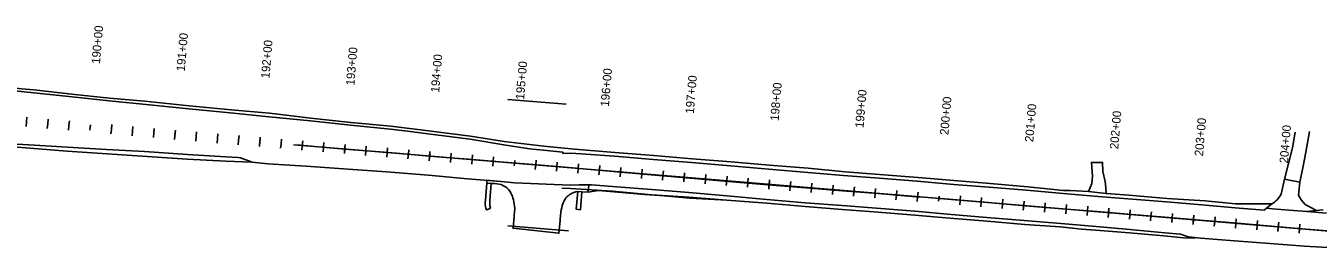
# Model space of a CAD drawing. Extents: x 20499880 to 20505309, y 7953507 to 7955507.
# Drawn here: x 20502629 to 20504147, y 7953670 to 7953931 of the extents above; entities that cross this region are included whole.
import ezdxf

# ---------------------------------------------------------------- set-up
doc = ezdxf.new("R2010")
doc.units = 0
for name, color, linetype in [('Alignment', 7, 'Continuous'), ('Curb', 7, 'Continuous'), ('Draft_0', 7, 'Continuous'), ('Entrance', 7, 'Continuous')]:
    doc.layers.add(name, color=color, linetype=linetype)

msp = doc.modelspace()

# ---------------------------------------------------------------- linework, layer by layer
at = {"layer": 'Alignment'}
for p, q in [((20502705.2, 7953814.8), (20502704.6, 7953808.7)), ((20502705.2, 7953814.8), (20502704.6, 7953808.7)), ((20502804.5, 7953803), (20502805, 7953808.5)), ((20502804.5, 7953803), (20502804.1, 7953797.6)), ((20502904.2, 7953794.7), (20502903.7, 7953789.3)), ((20502904.2, 7953794.7), (20502904.6, 7953800.2)), ((20503003.8, 7953786.4), (20503004.3, 7953791.8)), ((20503003.8, 7953786.4), (20503003.4, 7953781)), ((20503103.5, 7953778.1), (20503103, 7953772.6)), ((20503103.5, 7953778.1), (20503103.9, 7953783.5)), ((20503203.4, 7953772.8), (20503202.9, 7953766.7)), ((20503203.4, 7953772.8), (20503202.9, 7953766.7)), ((20503302.8, 7953761.5), (20503302.3, 7953756)), ((20503302.8, 7953761.5), (20503303.3, 7953766.9)), ((20503402.5, 7953753.1), (20503402, 7953747.7)), ((20503402.5, 7953753.1), (20503402.9, 7953758.6)), ((20503502.1, 7953744.8), (20503502.6, 7953750.3)), ((20503502.1, 7953744.8), (20503501.7, 7953739.4)), ((20503601.8, 7953736.5), (20503601.3, 7953731.1)), ((20503601.8, 7953736.5), (20503602.2, 7953741.9)), ((20503701.7, 7953731.2), (20503701.2, 7953725.1)), ((20503701.7, 7953731.2), (20503701.2, 7953725.1)), ((20503801.1, 7953719.9), (20503800.6, 7953714.4)), ((20503801.1, 7953719.9), (20503801.5, 7953725.3)), ((20503900.7, 7953711.6), (20503901.2, 7953717)), ((20503900.7, 7953711.6), (20503900.3, 7953706.1)), ((20504000.4, 7953703.2), (20503999.9, 7953697.8)), ((20504000.4, 7953703.2), (20504000.8, 7953708.7)), ((20504100, 7953694.9), (20504100.5, 7953700.4)), ((20504100, 7953694.9), (20504099.6, 7953689.5))]:
    msp.add_line(p, q, dxfattribs=at)
at = {"layer": 'Curb'}
for p, q in [((20503195.4, 7953844.6), (20503263.7, 7953838.9)), ((20504116.6, 7953787.9), (20504119.9, 7953806.1)), ((20504112.1, 7953769.2), (20504116.6, 7953787.9)), ((20504107.2, 7953750.8), (20504112.1, 7953769.2)), ((20504103.3, 7953733.3), (20504107.2, 7953750.8)), ((20504107.2, 7953750.8), (20504125.4, 7953747.6)), ((20504086.1, 7953717.1), (20504092.3, 7953721.9)), ((20503195.2, 7953696.3), (20503266.6, 7953690.4))]:
    msp.add_line(p, q, dxfattribs=at)
for points in [[(20502599.2, 7953860.1), (20502613.4, 7953858.2), (20502624.3, 7953857.2), (20502638.7, 7953856), (20502686.8, 7953850.5), (20502727.7, 7953846), (20502769, 7953842.4), (20502821.2, 7953837), (20502870.6, 7953832.3), (20502915.4, 7953828.5), (20502964.1, 7953822.6), (20503011.1, 7953817.6)], [(20504156.6, 7953711.2), (20504133.6, 7953713.2), (20504112.7, 7953714.7), (20504093.2, 7953716.3), (20504086.1, 7953717.1), (20504083.6, 7953714.6), (20504049.4, 7953717.4), (20504010.1, 7953720.8), (20503968.9, 7953724.2), (20503928.6, 7953727.3), (20503888.5, 7953730.8), (20503847.4, 7953734.3), (20503804.4, 7953737.9), (20503760.6, 7953741.4), (20503719.1, 7953744.8), (20503675.9, 7953748.5), (20503631.5, 7953752.1), (20503589.5, 7953755.4), (20503547.6, 7953758.8), (20503501.9, 7953762.8), (20503456.9, 7953766.5), (20503411.1, 7953770.4), (20503366, 7953774.1), (20503320.7, 7953777.8), (20503281.6, 7953780.8), (20503269, 7953781.5), (20503260.1, 7953781.3), (20503260, 7953782.6), (20503237.1, 7953784.9), (20503220.9, 7953786.7), (20503190.6, 7953791.2), (20503151.2, 7953797.9), (20503104.5, 7953803.8), (20503080.8, 7953807), (20503057.7, 7953809.7), (20503010.5, 7953814.4), (20502963.6, 7953819.3), (20502915.2, 7953824.2), (20502869.4, 7953828.7), (20502820.8, 7953833.4), (20502774.8, 7953838.1), (20502727.2, 7953842.9), (20502683.7, 7953847.7), (20502605, 7953855.9)], [(20503273.7, 7953786.1), (20503237.5, 7953789.7), (20503191, 7953795.2), (20503151.5, 7953801.3), (20503105.3, 7953807.3), (20503057.9, 7953813.2), (20503011.1, 7953817.6)], [(20504136.5, 7953807.1), (20504132.4, 7953782.5), (20504129.2, 7953766.4), (20504125.4, 7953747.6), (20504123.9, 7953732.1), (20504126.9, 7953726.7), (20504131.6, 7953721.3), (20504143.9, 7953714.5), (20504144.2, 7953713.9)], [(20502895, 7953771), (20502894.8, 7953770.8), (20502864.2, 7953772), (20502819, 7953774.4), (20502678, 7953783.9), (20502590, 7953791.1), (20502585.9, 7953791.2)], [(20503203, 7953746.5), (20503187.4, 7953748.3), (20503148, 7953751.4), (20503102.1, 7953755.6), (20503052.7, 7953759.7), (20503007.9, 7953762.8), (20502958.4, 7953766.1), (20502913.6, 7953768.9), (20502895, 7953771), (20502884.5, 7953774.9), (20502881.3, 7953776.1), (20502878.6, 7953776.4), (20502864.4, 7953777.3), (20502819.3, 7953780.1), (20502768.9, 7953783.3), (20502724.3, 7953785.9), (20502678.2, 7953788.5), (20502632.9, 7953791.3), (20502589.7, 7953793.5)], [(20503321, 7953782.2), (20503273.7, 7953786.1)], [(20503677.2, 7953752.9), (20503631.8, 7953756.3), (20503591.3, 7953759.6), (20503547.9, 7953763.8), (20503502.2, 7953767.6), (20503457.4, 7953771.5), (20503411.6, 7953774.8), (20503366.7, 7953778.8), (20503321, 7953782.2)], [(20503877.3, 7953736.5), (20503881.1, 7953745.7), (20503881.9, 7953754.6), (20503880.5, 7953770.7), (20503893.6, 7953770.7), (20503894, 7953760.1), (20503896.9, 7953748.4), (20503897.6, 7953740.9), (20503897.9, 7953734.2)], [(20504171.6, 7953670), (20504130.8, 7953672.4), (20504090.2, 7953675.6), (20504048.5, 7953678.4), (20504008.7, 7953681.6), (20503994, 7953683.1), (20503985, 7953686.5), (20503966.6, 7953687.9), (20503925.7, 7953691.8), (20503886.2, 7953695.4), (20503844.6, 7953699), (20503801.7, 7953702.5), (20503757.8, 7953706.1), (20503715.9, 7953709.6), (20503673.4, 7953713.3), (20503628.1, 7953717.1), (20503587.8, 7953720), (20503544.5, 7953723.1), (20503499.4, 7953727), (20503452.4, 7953731.3), (20503407.8, 7953735.3), (20503363.9, 7953738.9), (20503318.1, 7953742.2), (20503293.5, 7953744.4), (20503278.6, 7953744.4), (20503268.7, 7953744.1), (20503203, 7953746.5)], [(20503677.2, 7953752.9), (20503719, 7953749.4), (20503761.8, 7953745.7), (20503806, 7953742.1), (20503847.7, 7953737.8), (20503855.1, 7953737.5), (20503877.3, 7953736.5)], [(20503844, 7953694.9), (20503802.2, 7953697.7), (20503758.1, 7953701.7), (20503714.5, 7953705.3), (20503673.4, 7953708.8), (20503630.1, 7953712.2), (20503587.9, 7953715.4), (20503544.3, 7953719), (20503499.4, 7953722.8), (20503452.4, 7953726.3), (20503407.8, 7953729.7), (20503364.6, 7953732.7), (20503318.3, 7953737), (20503268.8, 7953739.9), (20503258.6, 7953740.4)], [(20503897.9, 7953734.2), (20503877.3, 7953736.5)], [(20503897.9, 7953734.2), (20503924.7, 7953732), (20503969.4, 7953728.4), (20504014.1, 7953725.5), (20504049.8, 7953722.2), (20504092.3, 7953721.9)], [(20503868.8, 7953692.2), (20503844, 7953694.9)], [(20503868.8, 7953692.2), (20503885.2, 7953691.1), (20503925.4, 7953688), (20503965.6, 7953684.3), (20503988.7, 7953682.1), (20504001.8, 7953681.5), (20504002, 7953682.3)]]:
    msp.add_lwpolyline(points, dxfattribs=at)
msp.add_ellipse((20504077.5, 7953747.2), major_axis=(16, 24.7), ratio=0.997668, start_param=4.247423, end_param=4.789994, dxfattribs=at)
at = {"layer": 'Draft_0'}
for points in [[(20502624.3, 7953857.2), (20502638.7, 7953856), (20502686.8, 7953850.5), (20502727.7, 7953846), (20502769, 7953842.4), (20502821.2, 7953837), (20502870.6, 7953832.3), (20502915.4, 7953828.5), (20502964.1, 7953822.6), (20503011.1, 7953817.6), (20503057.9, 7953813.2), (20503105.3, 7953807.3), (20503151.5, 7953801.3), (20503191, 7953795.2), (20503237.5, 7953789.7), (20503273.7, 7953786.1), (20503321, 7953782.2), (20503366.7, 7953778.8), (20503411.6, 7953774.8), (20503457.4, 7953771.5), (20503502.2, 7953767.6), (20503547.9, 7953763.8), (20503591.3, 7953759.6), (20503631.8, 7953756.3), (20503677.2, 7953752.9), (20503719, 7953749.4), (20503761.8, 7953745.7), (20503806, 7953742.1), (20503847.7, 7953737.8), (20503855.1, 7953737.5), (20503877.3, 7953736.5), (20503897.9, 7953734.2), (20503924.7, 7953732), (20503969.4, 7953728.4), (20504014.1, 7953725.5), (20504049.8, 7953722.2), (20504092.3, 7953721.9), (20504086.1, 7953717.1), (20504083.6, 7953714.6), (20504049.4, 7953717.4), (20504010.1, 7953720.8), (20503968.9, 7953724.2), (20503928.6, 7953727.3), (20503888.5, 7953730.8), (20503847.4, 7953734.3), (20503804.4, 7953737.9), (20503760.6, 7953741.4), (20503719.1, 7953744.8), (20503675.9, 7953748.5), (20503631.5, 7953752.1), (20503589.5, 7953755.4), (20503547.6, 7953758.8), (20503501.9, 7953762.8), (20503456.9, 7953766.5), (20503411.1, 7953770.4), (20503366, 7953774.1), (20503320.7, 7953777.8), (20503281.6, 7953780.8), (20503269, 7953781.5), (20503260.1, 7953781.3), (20503260, 7953782.6), (20503237.1, 7953784.9), (20503220.9, 7953786.7), (20503190.6, 7953791.2), (20503151.2, 7953797.9), (20503104.5, 7953803.8), (20503080.8, 7953807), (20503057.7, 7953809.7), (20503010.5, 7953814.4), (20502963.6, 7953819.3), (20502915.2, 7953824.2), (20502869.4, 7953828.7), (20502820.8, 7953833.4), (20502774.8, 7953838.1), (20502727.2, 7953842.9), (20502683.7, 7953847.7), (20502605, 7953855.9)], [(20502605, 7953855.9), (20502683.7, 7953847.7), (20502727.2, 7953842.9), (20502774.8, 7953838.1), (20502820.8, 7953833.4), (20502869.4, 7953828.7), (20502915.2, 7953824.2), (20502963.6, 7953819.3), (20503010.5, 7953814.4), (20503057.7, 7953809.7), (20503080.8, 7953807), (20503104.5, 7953803.8), (20503151.2, 7953797.9), (20503190.6, 7953791.2), (20503220.9, 7953786.7), (20503237.1, 7953784.9), (20503260, 7953782.6), (20503260.1, 7953781.3), (20503269, 7953781.5), (20503281.6, 7953780.8), (20503320.7, 7953777.8), (20503366, 7953774.1), (20503411.1, 7953770.4), (20503456.9, 7953766.5), (20503501.9, 7953762.8), (20503547.6, 7953758.8), (20503589.5, 7953755.4), (20503631.5, 7953752.1), (20503675.9, 7953748.5), (20503719.1, 7953744.8), (20503760.6, 7953741.4), (20503804.4, 7953737.9), (20503847.4, 7953734.3), (20503888.5, 7953730.8), (20503928.6, 7953727.3), (20503968.9, 7953724.2), (20504010.1, 7953720.8), (20504049.4, 7953717.4), (20504083.6, 7953714.6), (20504086.1, 7953717.1), (20504093.2, 7953716.3), (20504112.7, 7953714.7), (20504133.6, 7953713.2), (20504152.7, 7953715)], [(20504171.6, 7953670), (20504130.8, 7953672.4), (20504090.2, 7953675.6), (20504048.5, 7953678.4), (20504008.7, 7953681.6), (20503994, 7953683.1), (20503985, 7953686.5), (20503966.6, 7953687.9), (20503925.7, 7953691.8), (20503886.2, 7953695.4), (20503844.6, 7953699), (20503801.7, 7953702.5), (20503757.8, 7953706.1), (20503715.9, 7953709.6), (20503673.4, 7953713.3), (20503628.1, 7953717.1), (20503587.8, 7953720), (20503544.5, 7953723.1), (20503499.4, 7953727), (20503452.4, 7953731.3), (20503407.8, 7953735.3), (20503363.9, 7953738.9), (20503318.1, 7953742.2), (20503293.5, 7953744.4), (20503278.6, 7953744.4), (20503268.7, 7953744.1), (20503268.5, 7953744.1), (20503268.6, 7953744.2), (20503268.5, 7953744.1), (20503203, 7953746.5), (20503187.4, 7953748.3), (20503148, 7953751.4), (20503102.1, 7953755.6), (20503052.7, 7953759.7), (20503007.9, 7953762.8), (20502958.4, 7953766.1), (20502913.6, 7953768.9), (20502895, 7953771), (20502884.5, 7953774.9), (20502881.3, 7953776.1), (20502878.6, 7953776.4), (20502864.4, 7953777.3), (20502819.3, 7953780.1), (20502768.9, 7953783.3), (20502724.3, 7953785.9), (20502678.2, 7953788.5), (20502632.9, 7953791.3), (20502589.7, 7953793.5)], [(20504172.5, 7953689.1), (20504132.3, 7953692.3), (20504091.7, 7953695.9), (20504047.3, 7953699.8), (20504008.2, 7953702.8), (20503966.6, 7953706.2), (20503927.9, 7953709.4), (20503886.9, 7953713), (20503846.4, 7953716.2), (20503803.1, 7953719.8), (20503759.2, 7953723.5), (20503717.7, 7953727), (20503679, 7953730.1), (20503284, 7953763), (20503271.4, 7953764.2), (20503234.3, 7953767.3), (20503190.1, 7953771), (20503149.2, 7953774.3), (20503132.6, 7953775.7), (20503081.9, 7953779.9), (20503055.3, 7953782.3), (20503029.7, 7953784.2), (20502968.4, 7953789.4), (20502960.7, 7953790), (20502951.5, 7953791.1), (20502944.1, 7953791.4), (20502968.4, 7953789.4), (20503008.9, 7953785.9), (20503029.7, 7953784.2), (20503081.9, 7953779.9), (20503103.4, 7953778), (20503132.6, 7953775.7), (20503284, 7953763), (20503319.4, 7953759.8), (20503363.8, 7953756.1), (20503409.4, 7953752), (20503454.4, 7953748.4), (20503500.6, 7953744.5), (20503545.3, 7953741), (20503588.5, 7953737.2), (20503630.1, 7953734.1), (20503674.8, 7953730.4), (20503679, 7953730.1), (20504248, 7953682.6)], [(20503175.9, 7953745.9), (20503174.2, 7953726), (20503174.1, 7953724.3), (20503174.1, 7953722), (20503174.4, 7953719.7), (20503174.9, 7953717.1), (20503174.8, 7953716.7), (20503170.2, 7953714.8), (20503169.6, 7953716.9), (20503169.1, 7953718.8), (20503168.9, 7953720.6), (20503168.8, 7953722.1), (20503168.8, 7953723.7), (20503169, 7953726.5), (20503170.8, 7953746.2), (20503175.8, 7953745.9)], [(20503194.7, 7953740.7), (20503187.4, 7953744.9), (20503180, 7953745.7), (20503175.9, 7953745.9), (20503170.9, 7953746.2), (20503170.2, 7953749.7), (20503187.5, 7953748.3), (20503203, 7953746.5), (20503268.7, 7953744.1), (20503278.7, 7953744.4), (20503290.3, 7953744.4), (20503289.7, 7953735.8), (20503282.4, 7953736), (20503277.4, 7953736.5), (20503275.1, 7953736), (20503273, 7953735.4), (20503270.9, 7953734.5), (20503269, 7953733.5), (20503267.5, 7953732.5), (20503266.1, 7953731.4), (20503264.8, 7953730.2), (20503263.6, 7953728.9), (20503262.5, 7953727.4), (20503261.5, 7953725.7), (20503260.6, 7953723.8), (20503259.9, 7953721.9), (20503259.2, 7953719.9), (20503258.6, 7953717.4), (20503258, 7953714.8), (20503257.6, 7953712.2), (20503257.1, 7953708.2), (20503256.8, 7953704.2), (20503256.7, 7953703.2), (20503256.7, 7953702.8), (20503256.3, 7953698.7), (20503255.3, 7953687.4), (20503201.5, 7953693.3), (20503201.5, 7953693.4), (20503202.7, 7953707.1), (20503202.7, 7953707.7), (20503202.7, 7953708.6), (20503203.4, 7953716.7), (20503202.4, 7953724.5)]]:
    msp.add_lwpolyline(points, dxfattribs=at)
for points in [[(20502678, 7953783.9), (20502590, 7953791.1), (20502585.9, 7953791.2), (20502589.7, 7953793.4), (20502589.7, 7953793.5), (20502632.9, 7953791.3), (20502678.2, 7953788.5), (20502724.3, 7953785.9), (20502768.9, 7953783.3), (20502819.3, 7953780.1), (20502864.4, 7953777.3), (20502878.6, 7953776.4), (20502881.3, 7953776.1), (20502884.5, 7953774.9), (20502895, 7953771), (20502894.8, 7953770.8), (20502864.2, 7953772), (20502819, 7953774.4)], [(20503280.8, 7953715), (20503275.6, 7953715.6), (20503277.4, 7953736.5), (20503277.4, 7953736.5), (20503282.4, 7953736)], [(20503290.3, 7953744.4), (20503293.5, 7953744.4), (20503318.1, 7953742.2), (20503363.9, 7953738.9), (20503407.8, 7953735.3), (20503452.4, 7953731.3), (20503499.4, 7953727), (20503544.5, 7953723.1), (20503587.8, 7953720), (20503628.1, 7953717.1), (20503673.4, 7953713.3), (20503715.9, 7953709.6), (20503757.8, 7953706.1), (20503801.7, 7953702.5), (20503844.6, 7953699), (20503886.2, 7953695.4), (20503925.7, 7953691.8), (20503966.6, 7953687.9), (20503985, 7953686.5), (20503994, 7953683.1), (20504002, 7953682.3), (20504001.8, 7953681.5), (20503988.7, 7953682.1), (20503965.6, 7953684.3), (20503925.4, 7953688), (20503885.2, 7953691.1), (20503868.8, 7953692.2), (20503844, 7953694.9), (20503802.2, 7953697.7), (20503758.1, 7953701.7), (20503714.5, 7953705.3), (20503673.4, 7953708.8), (20503630.1, 7953712.2), (20503587.9, 7953715.4), (20503544.3, 7953719), (20503499.4, 7953722.8), (20503452.4, 7953726.3), (20503408.9, 7953728.5), (20503378.8, 7953731.4), (20503356.2, 7953733), (20503302, 7953737.7), (20503289.7, 7953735.8)]]:
    msp.add_lwpolyline(points, close=True, dxfattribs=at)
msp.add_arc((20503175.6, 7953742.5), 3.46, 84.1604, 86.0777, dxfattribs=at)
msp.add_ellipse((20503171.6, 7953719.7), major_axis=(-11.8, 28.9), ratio=0.998309, start_param=4.476933, end_param=5.059077, dxfattribs=at)
at = {"layer": 'Entrance'}
for p, q in [((20502630.2, 7953818.2), (20502630.7, 7953823.6)), ((20502630.2, 7953818.2), (20502629.7, 7953812.8)), ((20502655.1, 7953816), (20502654.6, 7953810.6)), ((20502655.1, 7953816), (20502655.6, 7953821.5)), ((20502680, 7953813.9), (20502679.5, 7953808.4)), ((20502680, 7953813.9), (20502680.5, 7953819.3)), ((20502705.2, 7953814.8), (20502704.6, 7953808.7)), ((20502705.2, 7953814.8), (20502704.6, 7953808.7)), ((20502729.8, 7953809.5), (20502729.3, 7953804.1)), ((20502729.8, 7953809.5), (20502730.3, 7953815)), ((20502754.7, 7953807.4), (20502754.2, 7953801.9)), ((20502754.7, 7953807.4), (20502755.2, 7953812.8)), ((20502779.6, 7953805.2), (20502780.1, 7953810.6)), ((20502829.4, 7953801), (20502829.9, 7953806.4)), ((20502779.6, 7953805.2), (20502779.2, 7953799.8)), ((20502804.8, 7953806.1), (20502804.3, 7953800)), ((20502804.8, 7953806.1), (20502804.3, 7953800)), ((20502829.4, 7953801), (20502829, 7953795.5)), ((20502854.4, 7953798.9), (20502853.9, 7953793.4)), ((20502854.4, 7953798.9), (20502854.8, 7953804.3)), ((20502879.3, 7953796.8), (20502878.8, 7953791.4)), ((20502879.3, 7953796.8), (20502879.7, 7953802.2)), ((20502904.4, 7953797.8), (20502903.9, 7953791.7)), ((20502904.4, 7953797.8), (20502903.9, 7953791.7)), ((20502929.1, 7953792.6), (20502928.6, 7953787.2)), ((20502929.1, 7953792.6), (20502929.6, 7953798.1)), ((20502954, 7953790.6), (20502954.5, 7953796)), ((20502978.9, 7953788.5), (20502979.4, 7953793.9)), ((20502954, 7953790.6), (20502953.6, 7953785.1)), ((20502978.9, 7953788.5), (20502978.5, 7953783)), ((20503004.1, 7953789.5), (20503003.6, 7953783.4)), ((20503004.1, 7953789.5), (20503003.6, 7953783.4)), ((20503028.8, 7953784.3), (20503028.3, 7953778.9)), ((20503028.8, 7953784.3), (20503029.2, 7953789.8)), ((20503053.7, 7953782.2), (20503053.2, 7953776.8)), ((20503053.7, 7953782.2), (20503054.1, 7953787.7)), ((20503078.6, 7953780.2), (20503078.1, 7953774.7)), ((20503078.6, 7953780.2), (20503079, 7953785.6)), ((20503103.7, 7953781.1), (20503103.2, 7953775)), ((20503103.7, 7953781.1), (20503103.2, 7953775)), ((20503128.4, 7953776), (20503128, 7953770.6)), ((20503128.4, 7953776), (20503128.9, 7953781.5)), ((20503153.3, 7953773.9), (20503153.8, 7953779.4)), ((20503178.2, 7953771.9), (20503178.7, 7953777.3)), ((20503153.3, 7953773.9), (20503152.9, 7953768.5)), ((20503178.2, 7953771.9), (20503177.8, 7953766.4)), ((20503203.4, 7953772.8), (20503202.9, 7953766.7)), ((20503203.4, 7953772.8), (20503202.9, 7953766.7)), ((20503228.1, 7953767.7), (20503227.6, 7953762.3)), ((20503228.1, 7953767.7), (20503228.5, 7953773.1)), ((20503253, 7953765.6), (20503252.5, 7953760.2)), ((20503253, 7953765.6), (20503253.4, 7953771.1)), ((20503277.9, 7953763.5), (20503277.4, 7953758.1)), ((20503277.9, 7953763.5), (20503278.3, 7953769)), ((20503303.1, 7953764.5), (20503302.5, 7953758.4)), ((20503303.1, 7953764.5), (20503302.5, 7953758.4)), ((20503327.7, 7953759.4), (20503328.2, 7953764.8)), ((20503352.6, 7953757.3), (20503353.1, 7953762.7)), ((20503327.7, 7953759.4), (20503327.3, 7953753.9)), ((20503352.6, 7953757.3), (20503352.2, 7953751.9)), ((20503377.5, 7953755.2), (20503377.1, 7953749.8)), ((20503377.5, 7953755.2), (20503378, 7953760.7)), ((20503402.7, 7953756.2), (20503402.2, 7953750.1)), ((20503402.7, 7953756.2), (20503402.2, 7953750.1)), ((20503427.4, 7953751.1), (20503426.9, 7953745.6)), ((20503427.4, 7953751.1), (20503427.8, 7953756.5)), ((20503452.3, 7953749), (20503451.8, 7953743.5)), ((20503452.3, 7953749), (20503452.7, 7953754.4)), ((20503477.2, 7953746.9), (20503476.7, 7953741.5)), ((20503477.2, 7953746.9), (20503477.6, 7953752.3)), ((20503502.4, 7953747.9), (20503501.9, 7953741.8)), ((20503502.4, 7953747.9), (20503501.9, 7953741.8)), ((20503527, 7953742.7), (20503527.5, 7953748.2)), ((20503551.9, 7953740.7), (20503552.4, 7953746.1)), ((20503527, 7953742.7), (20503526.6, 7953737.3)), ((20503551.9, 7953740.7), (20503551.5, 7953735.2)), ((20503576.8, 7953738.6), (20503576.4, 7953733.1)), ((20503576.8, 7953738.6), (20503577.3, 7953744)), ((20503602, 7953739.6), (20503601.5, 7953733.5)), ((20503602, 7953739.6), (20503601.5, 7953733.5)), ((20503626.7, 7953734.4), (20503626.2, 7953729)), ((20503626.7, 7953734.4), (20503627.1, 7953739.9)), ((20503651.6, 7953732.3), (20503651.1, 7953726.9)), ((20503651.6, 7953732.3), (20503652, 7953737.8)), ((20503676.5, 7953730.3), (20503677, 7953735.7)), ((20503701.7, 7953731.2), (20503701.2, 7953725.1)), ((20503701.7, 7953731.2), (20503701.2, 7953725.1)), ((20503726.3, 7953726.1), (20503726.8, 7953731.6)), ((20503676.5, 7953730.3), (20503676, 7953724.8)), ((20503726.3, 7953726.1), (20503725.9, 7953720.7)), ((20503751.2, 7953724), (20503750.8, 7953718.6)), ((20503751.2, 7953724), (20503751.7, 7953729.5)), ((20503776.2, 7953722), (20503775.7, 7953716.5)), ((20503776.2, 7953722), (20503776.6, 7953727.4)), ((20503801.3, 7953722.9), (20503800.8, 7953716.8)), ((20503801.3, 7953722.9), (20503800.8, 7953716.8)), ((20503826, 7953717.8), (20503825.5, 7953712.4)), ((20503826, 7953717.8), (20503826.4, 7953723.2)), ((20503850.9, 7953715.7), (20503850.4, 7953710.3)), ((20503850.9, 7953715.7), (20503851.3, 7953721.2)), ((20503875.8, 7953713.6), (20503876.3, 7953719.1)), ((20503875.8, 7953713.6), (20503875.4, 7953708.2)), ((20503901, 7953714.6), (20503900.5, 7953708.5)), ((20503901, 7953714.6), (20503900.5, 7953708.5)), ((20503925.6, 7953709.5), (20503925.2, 7953704)), ((20503925.6, 7953709.5), (20503926.1, 7953714.9)), ((20503950.5, 7953707.4), (20503950.1, 7953702)), ((20503950.5, 7953707.4), (20503951, 7953712.8)), ((20503975.5, 7953705.3), (20503975, 7953699.9)), ((20503975.5, 7953705.3), (20503975.9, 7953710.8)), ((20504000.6, 7953706.3), (20504000.1, 7953700.2)), ((20504000.6, 7953706.3), (20504000.1, 7953700.2)), ((20504025.3, 7953701.2), (20504024.8, 7953695.7)), ((20504025.3, 7953701.2), (20504025.7, 7953706.6)), ((20504050.2, 7953699.1), (20504050.7, 7953704.5)), ((20504075.1, 7953697), (20504075.6, 7953702.4)), ((20504050.2, 7953699.1), (20504049.7, 7953693.6)), ((20504075.1, 7953697), (20504074.7, 7953691.6)), ((20504100.3, 7953698), (20504099.8, 7953691.9)), ((20504100.3, 7953698), (20504099.8, 7953691.9)), ((20504124.9, 7953692.8), (20504124.5, 7953687.4)), ((20504124.9, 7953692.8), (20504125.4, 7953698.3))]:
    msp.add_line(p, q, dxfattribs=at)

# ---------------------------------------------------------------- texts
at = {"layer": 'Alignment'}
for s, rotation, p in [('190+00', 85.0264, (20502716.4, 7953886)), ('195+00', 85.2296, (20503214.4, 7953844.1)), ('200+00', 85.2296, (20503712.6, 7953802.5))]:
    msp.add_text(s, height=10.02, rotation=rotation, dxfattribs=at).set_placement(p)
at = {"layer": 'Entrance'}
for s, rotation, p in [('190+00', 85.0264, (20502716.4, 7953886)), ('191+00', 85.0264, (20502816, 7953877.3)), ('192+00', 85.2296, (20502915.4, 7953869)), ('193+00', 85.2296, (20503015.1, 7953860.7)), ('194+00', 85.2296, (20503114.7, 7953852.4)), ('195+00', 85.2296, (20503214.4, 7953844.1)), ('196+00', 85.2296, (20503314, 7953835.8)), ('197+00', 85.2296, (20503413.7, 7953827.5)), ('198+00', 85.2296, (20503513.3, 7953819.1)), ('199+00', 85.2296, (20503613, 7953810.8)), ('200+00', 85.2296, (20503712.6, 7953802.5)), ('201+00', 85.2296, (20503812.3, 7953794.2)), ('202+00', 85.2296, (20503912, 7953785.9)), ('203+00', 85.2296, (20504011.6, 7953777.6)), ('204+00', 85.2296, (20504111.3, 7953769.2))]:
    msp.add_text(s, height=10.02, rotation=rotation, dxfattribs=at).set_placement(p)

doc.saveas('drawing.dxf')
